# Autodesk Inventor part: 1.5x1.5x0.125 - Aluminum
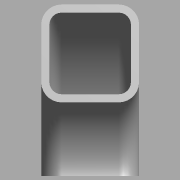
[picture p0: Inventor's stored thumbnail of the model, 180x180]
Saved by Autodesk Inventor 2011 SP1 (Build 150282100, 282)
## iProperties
Created: 2011-03
Part Number: 1.5x1.5x0.125 - Aluminum
Material: Default
Document SubType Name: Modeling
Designer: bamfomg
Density: 1 g/cm^3
Author: bamfomg
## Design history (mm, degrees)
derived "Square Tube Corners.ipt" dims "d2" = 19.05, "d3" = 19.05, "d6" = 3.175, "d7" = 3.175, "d8" = 3.175, "d12" = 90 deg, "d16" = 1.5875, "d18" = 30 deg, "ID_Rad" = 4.7625, "OD_Rad" = 7.9375, "Side_One" = 38.1, "Side_Two" = 38.1, "Thickness" = 3.175, "Bend_IDRad" = 28.575, "Bevel_Angl" = 30 deg, "Bevel_Dist" = 1.5875
body "Solid1"
feature "Solid1::Square Tube Corners.ipt" dims "d2" = 19.05, "d3" = 19.05, "d6" = 3.175, "d7" = 3.175, "d8" = 3.175, "d12" = 90 deg, "d16" = 1.5875, "d18" = 30 deg, "ID_Rad" = 4.7625, "OD_Rad" = 7.9375, "Side_One" = 38.1, "Side_Two" = 38.1, "Thickness" = 3.175, "Bend_IDRad" = 28.575, "Bevel_Angl" = 30 deg, "Bevel_Dist" = 1.5875, "ScaleForDerivedMember" = 10
tag "TaggingFeature1"
